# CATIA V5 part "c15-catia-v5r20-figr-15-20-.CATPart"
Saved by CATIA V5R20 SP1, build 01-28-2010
Part number: Part1
Bounding box of the stored display mesh (mm): x -81.56 to 85.56, y -36.965 to 25.965, z 0 to 42
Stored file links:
  D:\v5_r20\psrt_files_downloaded\c15\c15-catia-v5r20-figr-15-20-.CATPart
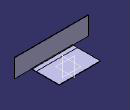
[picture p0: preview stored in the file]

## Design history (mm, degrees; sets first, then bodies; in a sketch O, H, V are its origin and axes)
SheetMetalParameters1: Thickness 1, BendRadius 1, KFactor 0.325257 {= log(min(100,max(20*SheetMetalParameters1.BendRadius,SheetMetalParameters1.Thickness)/SheetMetalParameters1.Thickness))/log(100)/2}, ReliefRadialLength 1, ReliefAxialLength 2, MinimumBendRadius 0
Body1 (main body)
  Sketch1 on xy-plane, origin (0, 0, 0), H (1, 0, 0), V (0, 1, 0)
    line L1 (-46.5596, 25.9646) -> (46.5596, 25.9646)
    line L2 (46.5596, 25.9646) -> (46.5596, -25.9646)
    line L3 (46.5596, -25.9646) -> (-46.5596, -25.9646)
    line L4 (-46.5596, -25.9646) -> (-46.5596, 25.9646)
    horizontal: L1 H, L3 H
    vertical: L2 V, L4 V
    symmetry: L1 L3 H, L4 L2 V
  Wall1: Thickness 1, Profile Sketch1
  d_NewWallOnEdge1: NewWallOnEdge_Edge edge [face of Wall1 | face of Wall1], NewWallOnEdge_Length 42, NewWallOnEdge_HeightLimitOffset 0, NewWallOnEdge_WidthOffset1 39, NewWallOnEdge_WidthOffset2 35, NewWallOnEdge_Angle 90, NewWallOnEdge_BendRadiusValue 1 {= SheetMetalParameters1.BendRadius}, NewWallOnEdge_BendTable SheetMetalParameters1, KFacteur 0.325257 {= log(min(100,max(20*d_NewWallOnEdge1.Radius,SheetMetalParameters1.Thickness)/SheetMetalParameters1.Thickness))/log(100)/2}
